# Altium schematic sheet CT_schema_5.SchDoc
size 305 x 256 mm
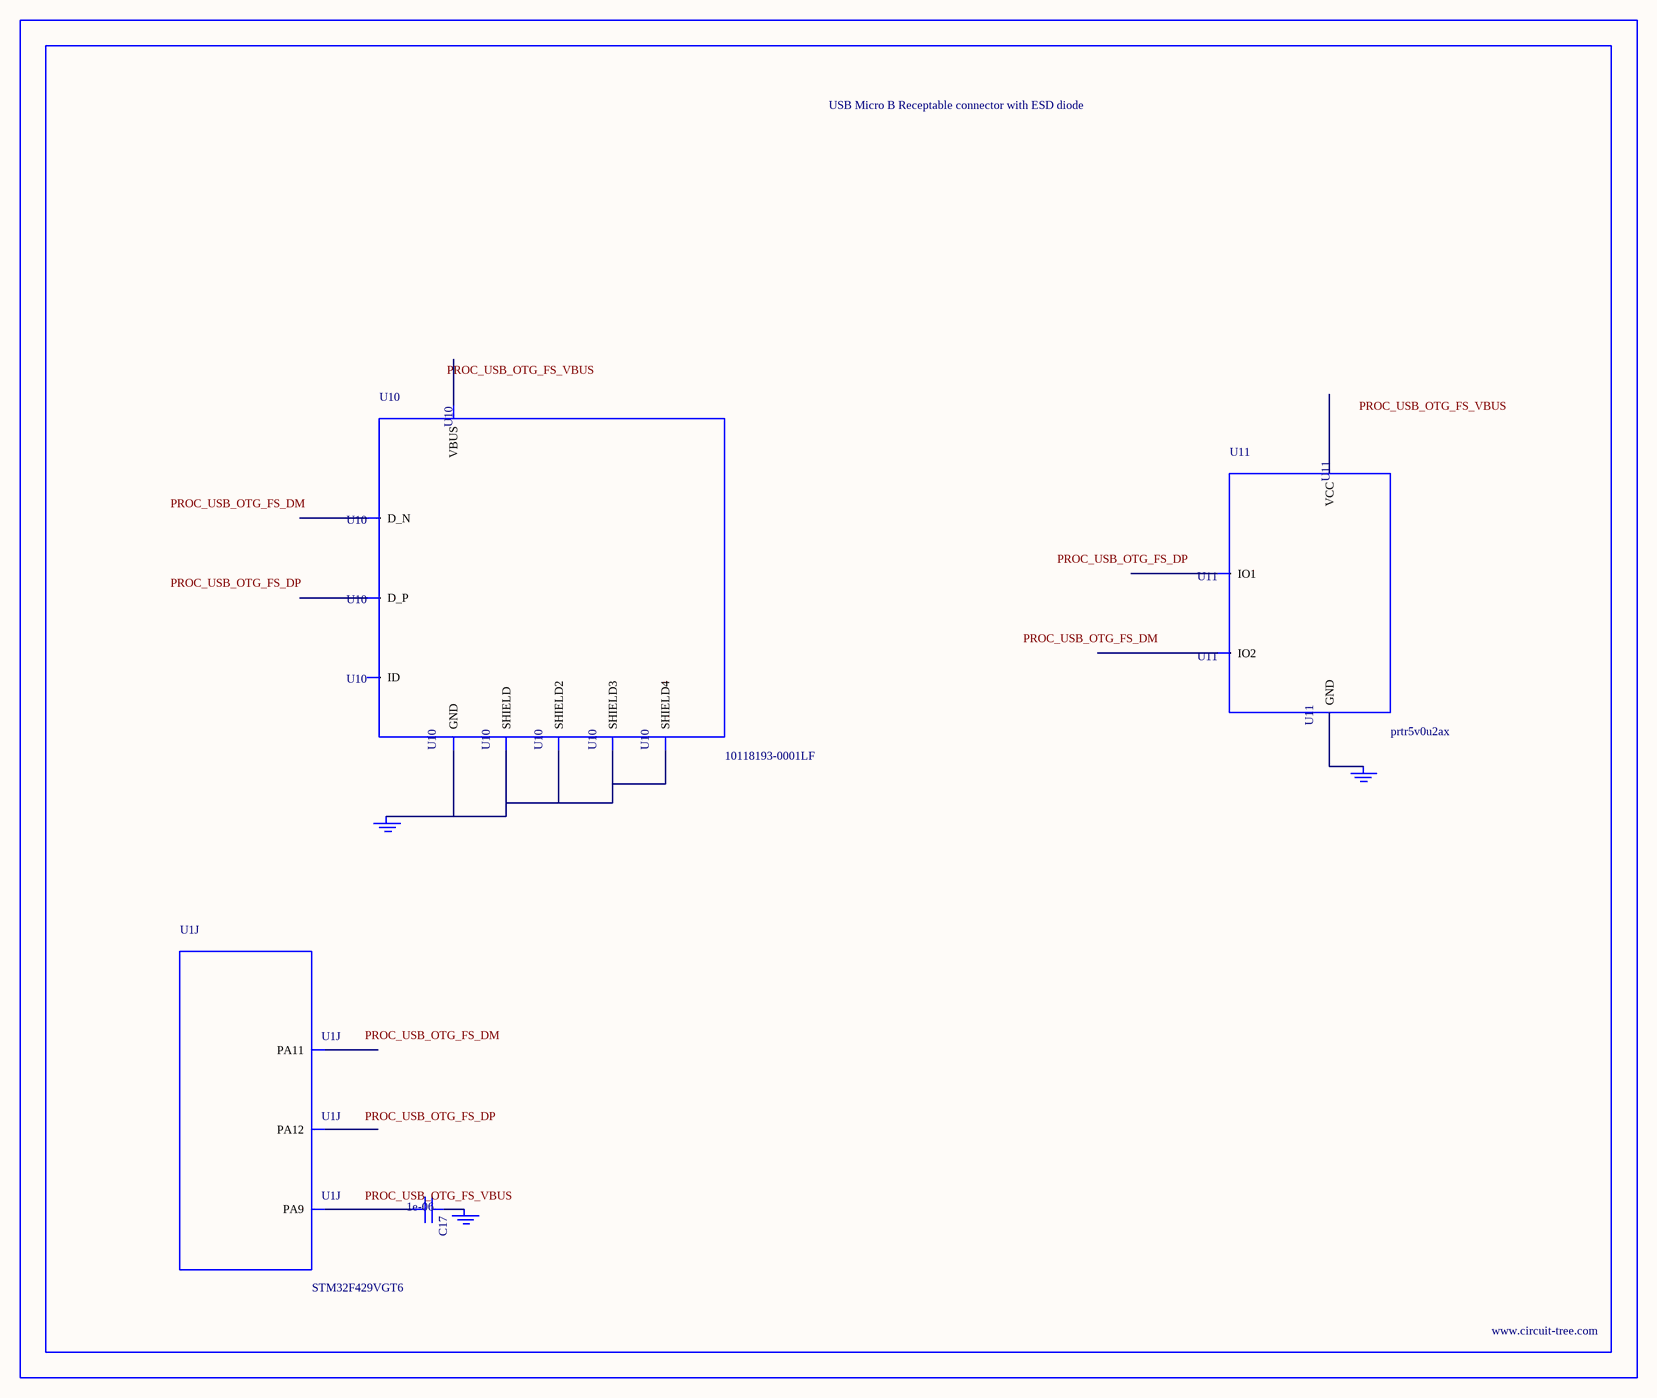
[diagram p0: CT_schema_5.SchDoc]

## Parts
BORDER4  (no value)
C17  1e-06  [C0603]
GND_INSTANCE_4_0  (no value)
GND_INSTANCE_4_1  (no value)
GND_INSTANCE_4_2  (no value)
U1  STM32F429VGT6  [LQFP100]  (part J of 10)
U10  10118193-0001LF  [FCI_10118193-0001LF]
U11  prtr5v0u2ax  [SOT143B]

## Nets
NetC17_1: C17.1 GND_INSTANCE_4_1.0(GND)
NetC17_2: C17.2 U1.68(PA9)
NetGND_INSTANCE_4_0_0: GND_INSTANCE_4_0.0(GND) U10.5(GND) U10.6(SHIELD) U10.7(SHIELD2) U10.8(SHIELD3) U10.9(SHIELD4)
NetGND_INSTANCE_4_2_0: GND_INSTANCE_4_2.0(GND) U11.1(GND)

Not connected (* = marked no-connect by the designer): U1 70(PA11) 71(PA12); U10 1(VBUS) 2(D_N) 3(D_P) 4(ID); U11 2(IO1) 3(IO2) 4(VCC)

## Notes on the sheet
- Labels drawn without touching a wire or pin: PROC_USB_OTG_FS_DM, PROC_USB_OTG_FS_DP, PROC_USB_OTG_FS_VBUS

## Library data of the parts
BORDER4 = BORDER_PAGE4
C17 = C0603C105K3RACTU
GND_INSTANCE_4_0-GND_INSTANCE_4_2 = GND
